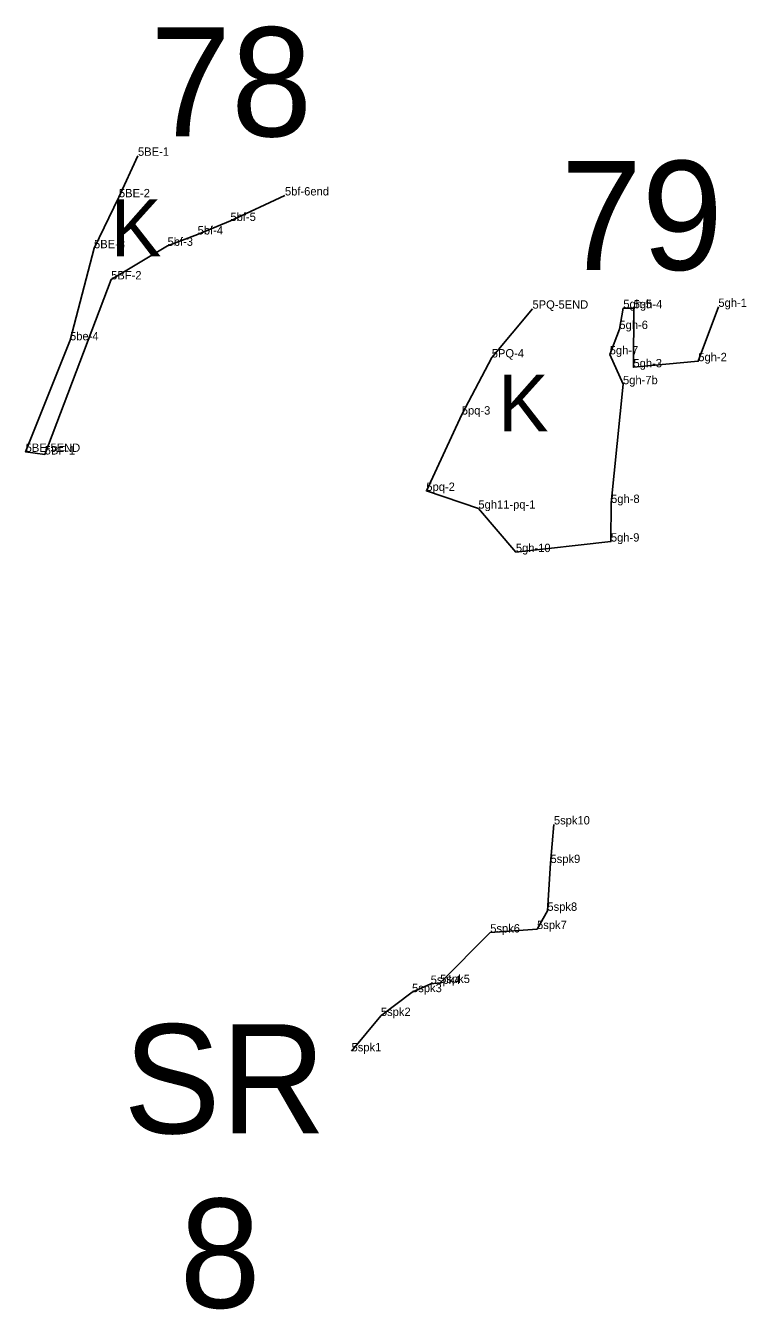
# Model space of a CAD drawing. Extents: x 2072529 to 2268796, y 436423 to 470406.
# Drawn here: x 2120838 to 2121270, y 448466 to 449235 of the extents above; entities that cross this region are included whole.
import ezdxf

# ---------------------------------------------------------------- set-up
doc = ezdxf.new("R2010")
doc.units = 0
for name, color, linetype in [('Default', 7, 'Continuous'), ('Exist Environmental Wetland Boundary Cogo Comment', 7, 'Continuous'), ('Exist Environmental Wetland Boundary Cogo Point CELL', 7, 'Continuous'), ('Exist Hydro Jurisdictional Stream or Body of Water NEU Mitigable Cogo Comment', 7, 'Continuous'), ('Old_Level_20', 7, 'Continuous'), ('Old_Level_52', 7, 'Continuous')]:
    doc.layers.add(name, color=color, linetype=linetype)

msp = doc.modelspace()

# ---------------------------------------------------------------- linework, layer by layer
at = {"layer": 'Old_Level_20'}
for p, q in [((2120904.9, 449157.04), (2120904.9, 449157.04)), ((2120893.47, 449132.19), (2120893.47, 449132.19)), ((2120993.04, 449133.29), (2120993.04, 449133.29)), ((2120960.35, 449117.99), (2120960.35, 449117.99)), ((2120940.67, 449109.9), (2120940.67, 449109.9)), ((2120878.54, 449101.66), (2120878.54, 449101.66)), ((2120922.64, 449103.11), (2120922.64, 449103.11)), ((2120888.83, 449082.98), (2120888.83, 449082.98)), ((2121141.49, 449065.44), (2121141.49, 449065.44)), ((2121195.96, 449065.76), (2121195.96, 449065.76)), ((2121202.21, 449065.68), (2121202.21, 449065.68)), ((2121252.98, 449066.51), (2121252.98, 449066.51)), ((2121193.61, 449053.26), (2121193.61, 449053.26)), ((2120864.15, 449046.5), (2120864.15, 449046.5)), ((2121187.81, 449038.05), (2121187.81, 449038.05)), ((2121117.07, 449036.22), (2121117.07, 449036.22)), ((2121202.06, 449030.31), (2121202.06, 449030.31)), ((2121240.94, 449033.98), (2121240.94, 449033.98)), ((2121195.78, 449020.2), (2121195.78, 449020.2)), ((2121099.11, 449001.99), (2121099.11, 449001.99)), ((2120848.98, 448978.07), (2120848.98, 448978.07)), ((2121077.84, 448956.25), (2121077.84, 448956.25)), ((2121109.06, 448945.63), (2121109.06, 448945.63)), ((2121188.65, 448949.04), (2121188.65, 448949.04)), ((2121188.51, 448925.88), (2121188.51, 448925.88)), ((2121131.53, 448919.61), (2121131.53, 448919.61)), ((2121154.35, 448756.4), (2121154.35, 448756.4)), ((2121152.3, 448733.29), (2121152.3, 448733.29)), ((2121150.45, 448704.64), (2121150.45, 448704.64)), ((2121116.15, 448691.64), (2121116.15, 448691.64)), ((2121144.24, 448693.72), (2121144.24, 448693.72)), ((2121080.45, 448660.87), (2121080.45, 448660.87)), ((2121086.13, 448661.4), (2121086.13, 448661.4)), ((2121069.27, 448655.91), (2121069.27, 448655.91)), ((2121050.58, 448641.64), (2121050.58, 448641.64)), ((2121032.99, 448620.46), (2121032.99, 448620.46))]:
    msp.add_line(p, q, dxfattribs=at)
for points in [[(2120904.9, 449157.04), (2120893.47, 449132.19), (2120878.54, 449101.66), (2120864.15, 449046.5), (2120837.53, 448979.65), (2120848.98, 448978.07)], [(2120993.04, 449133.29), (2120960.35, 449117.99), (2120940.67, 449109.9), (2120922.64, 449103.11), (2120888.83, 449082.98), (2120848.98, 448978.07)], [(2121141.49, 449065.44), (2121117.07, 449036.22), (2121099.11, 449001.99), (2121077.84, 448956.25), (2121109.06, 448945.63), (2121131.53, 448919.61), (2121188.51, 448925.88), (2121188.65, 448949.04), (2121195.78, 449020.2), (2121187.81, 449038.05), (2121193.61, 449053.26), (2121195.96, 449065.76), (2121202.21, 449065.68), (2121202.06, 449030.31), (2121240.94, 449033.98), (2121252.98, 449066.51)], [(2120837.53, 448979.65), (2120837.53, 448979.65), (2120837.53, 448979.65)]]:
    msp.add_lwpolyline(points, dxfattribs=at)
at = {"layer": 'Old_Level_52'}
msp.add_lwpolyline([(2121154.35, 448756.4), (2121152.3, 448733.29), (2121150.45, 448704.64), (2121144.24, 448693.72), (2121116.15, 448691.64), (2121086.13, 448661.4), (2121080.45, 448660.87), (2121069.27, 448655.91), (2121050.58, 448641.64), (2121032.99, 448620.46)], dxfattribs=at)

# ---------------------------------------------------------------- texts
at = {"layer": 'Default'}
for s, p in [('78', (2120912.16, 449168.7)), ('79', (2121158.5, 449088.68)), ('SR', (2120896.18, 448571.34)), ('8', (2120929.86, 448466.8))]:
    msp.add_text(s, height=65.34, dxfattribs=at).set_placement(p)
at = {"layer": 'Exist Environmental Wetland Boundary Cogo Comment'}
for s, p in [('5BE-1', (2120904.9, 449157.04)), ('5BE-2', (2120893.47, 449132.19)), ('5bf-6end', (2120993.04, 449133.29)), ('5bf-5', (2120960.35, 449117.99)), ('5bf-4', (2120940.67, 449109.9)), ('5BE-3', (2120878.54, 449101.66)), ('5bf-3', (2120922.64, 449103.11)), ('5BF-2', (2120888.83, 449082.98)), ('5PQ-5END', (2121141.49, 449065.44)), ('5gh-5', (2121195.96, 449065.76)), ('5gh-4', (2121202.21, 449065.68)), ('5gh-1', (2121252.98, 449066.51)), ('5gh-6', (2121193.61, 449053.26)), ('5be-4', (2120864.15, 449046.5)), ('5PQ-4', (2121117.07, 449036.22)), ('5gh-7', (2121187.81, 449038.05)), ('5gh-2', (2121240.94, 449033.98)), ('5gh-3', (2121202.06, 449030.31)), ('5gh-7b', (2121195.78, 449020.2)), ('5pq-3', (2121099.11, 449001.99)), ('5BE-5END', (2120837.53, 448979.65)), ('5BF-1', (2120848.98, 448978.07)), ('5pq-2', (2121077.84, 448956.25)), ('5gh-8', (2121188.65, 448949.04)), ('5gh11-pq-1', (2121109.06, 448945.63)), ('5gh-9', (2121188.51, 448925.88)), ('5gh-10', (2121131.53, 448919.61))]:
    msp.add_text(s, height=5, dxfattribs=at).set_placement(p)
at = {"layer": 'Exist Environmental Wetland Boundary Cogo Point CELL'}
for p in [(2120888.58, 449096.87), (2121120.84, 448991.88)]:
    msp.add_text('K', height=34, dxfattribs=at).set_placement(p)
at = {"layer": 'Exist Hydro Jurisdictional Stream or Body of Water NEU Mitigable Cogo Comment'}
for s, p in [('5spk10', (2121154.35, 448756.4)), ('5spk9', (2121152.3, 448733.29)), ('5spk8', (2121150.45, 448704.64)), ('5spk7', (2121144.24, 448693.72)), ('5spk6', (2121116.15, 448691.64)), ('5spk3', (2121069.27, 448655.91)), ('5spk4', (2121080.45, 448660.87)), ('5spk5', (2121086.13, 448661.4)), ('5spk2', (2121050.58, 448641.64)), ('5spk1', (2121032.99, 448620.46))]:
    msp.add_text(s, height=5, dxfattribs=at).set_placement(p)

doc.saveas('drawing.dxf')
